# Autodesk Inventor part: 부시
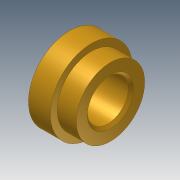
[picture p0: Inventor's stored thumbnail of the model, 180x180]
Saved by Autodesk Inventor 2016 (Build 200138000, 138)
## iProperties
Created: 2011-04
Part Number: 부시
Document SubType Name: Modeling
Density: 1 g/cm^3
Material: 일반
Appearance: 황동 - 새틴
Author: pww
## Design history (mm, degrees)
sketch "스케치1"
  geometry: L1 (0, 0)-(15, 0); L2 (0, 7.5)-(15, 7.5); L3 (15, 7.5)-(15, 12.5); L4 (15, 12.5)-(8, 12.5); L5 (8, 12.5)-(8, 15); L6 (8, 15)-(0, 15); L7 (0, 15)-(0, 7.5)
  constraints: 14 end point, 4 parallel, 2 vertical alignment, 1 horizontal, 1 perpendicular, 1 vertical
  dimensions: "d0" = 15 distance of L1.start L1.end; "d1" = 15 diameter of L2 L1; "d2" = 25 diameter of L4 L1; "d3" = 8 distance of L5.end L6.end; "d4" = 30 diameter of L6 L1
revolve "회전1" sketch "스케치1" stored, may be unused: angle "d5" = 90 deg
chamfer "모따기1" distance "d6" = 1; stored, may be unused: second distance "d7" = 2, angle "d8" = 45 deg
node "솔리드1"
